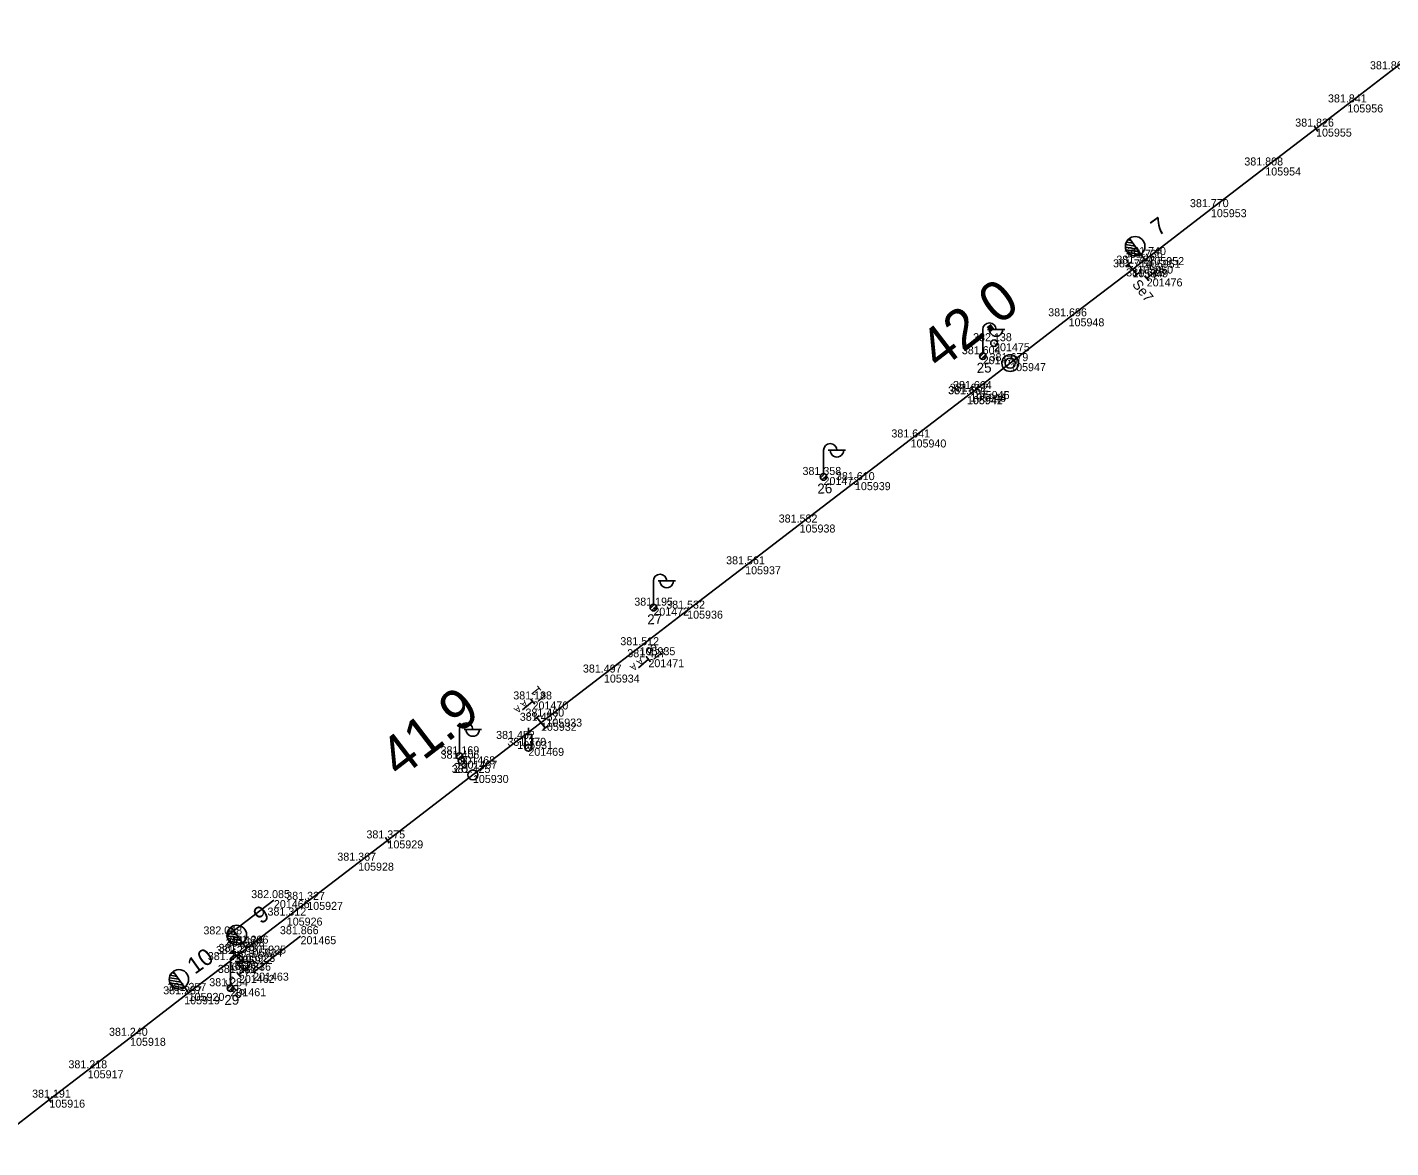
# Model space of a CAD drawing. Extents: x -514522 to -512811, y -1144589 to -1143575.
# Drawn here: x -513869.6 to -513665.2, y -1144029.6 to -1143861.6 of the extents above; entities that cross this region are included whole.
import ezdxf

# ---------------------------------------------------------------- set-up
doc = ezdxf.new("R2010")
doc.units = 0
for name, color, linetype in [('Vrstva 1', 7, 'Continuous'), ('Vrstva 17', 7, 'Continuous'), ('Vrstva 2', 7, 'Continuous'), ('Vrstva 25', 7, 'Continuous'), ('Vrstva 3', 7, 'Continuous'), ('Vrstva 50', 7, 'Continuous'), ('Vrstva 6', 7, 'Continuous'), ('Vrstva 60', 7, 'Continuous'), ('Vrstva 61', 7, 'Continuous'), ('Vrstva 7', 7, 'Continuous')]:
    doc.layers.add(name, color=color, linetype=linetype)

msp = doc.modelspace()

# ---------------------------------------------------------------- linework, layer by layer
at = {"layer": 'Vrstva 1'}
for p, q in [((-513665.21, -1143868.2), (-513656.61, -1143861.6)), ((-513671.7, -1143873.17), (-513665.21, -1143868.2)), ((-513676.4, -1143876.79), (-513671.7, -1143873.17)), ((-513684.01, -1143882.62), (-513676.4, -1143876.79)), ((-513692.16, -1143888.87), (-513684.01, -1143882.62)), ((-513701.53, -1143896.05), (-513692.16, -1143888.87)), ((-513703.19, -1143897.33), (-513702.07, -1143896.46)), ((-513702.07, -1143896.46), (-513701.53, -1143896.05)), ((-513713.49, -1143905.23), (-513703.93, -1143897.89)), ((-513703.93, -1143897.89), (-513703.19, -1143897.33)), ((-513722.25, -1143911.95), (-513713.49, -1143905.23)), ((-513727.7, -1143916.13), (-513722.25, -1143911.95)), ((-513737.18, -1143923.4), (-513728.7, -1143916.89)), ((-513728.7, -1143916.89), (-513728.23, -1143916.53)), ((-513728.23, -1143916.53), (-513727.7, -1143916.13)), ((-513745.52, -1143929.79), (-513737.18, -1143923.4)), ((-513753.81, -1143936.14), (-513745.52, -1143929.79)), ((-513761.98, -1143942.4), (-513753.81, -1143936.14)), ((-513770.67, -1143949.05), (-513761.98, -1143942.4)), ((-513777.8, -1143954.53), (-513770.67, -1143949.05)), ((-513783.15, -1143958.63), (-513777.8, -1143954.53)), ((-513791.78, -1143965.23), (-513783.15, -1143958.63)), ((-513796.14, -1143968.58), (-513792.59, -1143965.86)), ((-513792.59, -1143965.86), (-513791.78, -1143965.23)), ((-513802.79, -1143973.68), (-513796.14, -1143968.58)), ((-513815.6, -1143983.49), (-513802.79, -1143973.68)), ((-513819.99, -1143986.83), (-513815.6, -1143983.49)), ((-513827.62, -1143992.7), (-513819.99, -1143986.83)), ((-513830.69, -1143995.06), (-513827.62, -1143992.7)), ((-513836.16, -1143999.26), (-513830.69, -1143995.06)), ((-513836.73, -1143999.7), (-513836.16, -1143999.26)), ((-513839.38, -1144001.73), (-513838.19, -1144000.81)), ((-513838.19, -1144000.81), (-513837.78, -1144000.5)), ((-513837.78, -1144000.5), (-513836.73, -1143999.7)), ((-513845.4, -1144006.35), (-513839.38, -1144001.73)), ((-513854.18, -1144013.08), (-513846.07, -1144006.86)), ((-513846.07, -1144006.86), (-513845.4, -1144006.35)), ((-513860.53, -1144017.95), (-513854.18, -1144013.08)), ((-513866.28, -1144022.35), (-513860.53, -1144017.95)), ((-513875.66, -1144029.56), (-513866.28, -1144022.35))]:
    msp.add_line(p, q, dxfattribs=at)
at = {"layer": 'Vrstva 17'}
for p, q in [((-513839.76, -1143997.88), (-513832.62, -1143992.44)), ((-513835.74, -1144003.31), (-513828.63, -1143997.85))]:
    msp.add_line(p, q, dxfattribs=at)
at = {"layer": 'Vrstva 2'}
for p, q in [((-513676.13, -1143877.21), (-513676.68, -1143876.37)), ((-513703.22, -1143894.85), (-513704.97, -1143894.56)), ((-513703.53, -1143894.42), (-513704.95, -1143894.18)), ((-513702.91, -1143895.28), (-513704.88, -1143894.95)), ((-513703.84, -1143893.99), (-513704.84, -1143893.82)), ((-513704.15, -1143893.56), (-513704.62, -1143893.48)), ((-513702.66, -1143895.63), (-513704.37, -1143893.25)), ((-513704.37, -1143893.25), (-513702.66, -1143895.63)), ((-513702.76, -1143895.68), (-513704.63, -1143895.38)), ((-513702.66, -1143895.63), (-513702.07, -1143896.46)), ((-513702.66, -1143895.63), (-513702.66, -1143895.63)), ((-513815.32, -1143983.91), (-513815.87, -1143983.07)), ((-513838.19, -1143997.65), (-513839.62, -1143997.41)), ((-513838.5, -1143997.22), (-513839.5, -1143997.05)), ((-513838.81, -1143996.79), (-513839.28, -1143996.71)), ((-513837.33, -1143998.86), (-513839.03, -1143996.48)), ((-513839.03, -1143996.48), (-513837.33, -1143998.86)), ((-513837.88, -1143998.08), (-513839.63, -1143997.79)), ((-513837.57, -1143998.51), (-513839.54, -1143998.19)), ((-513837.42, -1143998.92), (-513839.3, -1143998.61)), ((-513837.33, -1143998.86), (-513836.73, -1143999.7)), ((-513837.33, -1143998.86), (-513837.33, -1143998.86)), ((-513847.48, -1144003.44), (-513847.95, -1144003.36)), ((-513846, -1144005.51), (-513847.7, -1144003.13)), ((-513847.7, -1144003.13), (-513846, -1144005.51)), ((-513846.55, -1144004.73), (-513848.31, -1144004.44)), ((-513846.86, -1144004.3), (-513848.29, -1144004.07)), ((-513846.25, -1144005.17), (-513848.22, -1144004.84)), ((-513847.17, -1144003.87), (-513848.18, -1144003.71)), ((-513846.1, -1144005.57), (-513847.97, -1144005.26)), ((-513846, -1144005.51), (-513845.4, -1144006.35)), ((-513846, -1144005.51), (-513846, -1144005.51)), ((-513866, -1144022.77), (-513866.55, -1144021.94))]:
    msp.add_line(p, q, dxfattribs=at)
for centre in [(-513703.52, -1143894.43), (-513838.18, -1143997.66), (-513846.86, -1144004.32)]:
    msp.add_circle(centre, 1.46, dxfattribs=at)
for centre in [(-513703.52, -1143894.44), (-513838.18, -1143997.67), (-513846.85, -1144004.32)]:
    msp.add_arc(centre, 1.46, 125.6292, 305.5901, dxfattribs=at)
at = {"layer": 'Vrstva 25'}
for p, q in [((-513726.36, -1143910.41), (-513726.36, -1143906.91)), ((-513725.66, -1143906.91), (-513723.06, -1143906.91)), ((-513726.84, -1143911.05), (-513726.22, -1143910.43)), ((-513726.6, -1143911.34), (-513725.92, -1143910.67)), ((-513750.23, -1143928.51), (-513750.23, -1143925.01)), ((-513749.53, -1143925.01), (-513746.93, -1143925.01)), ((-513750.71, -1143929.16), (-513750.09, -1143928.53)), ((-513750.47, -1143929.45), (-513749.79, -1143928.77)), ((-513775.74, -1143948.1), (-513775.74, -1143944.6)), ((-513775.04, -1143944.6), (-513772.44, -1143944.6)), ((-513776.22, -1143948.74), (-513775.6, -1143948.12)), ((-513775.98, -1143949.03), (-513775.3, -1143948.36)), ((-513804.81, -1143970.38), (-513804.81, -1143966.88)), ((-513804.11, -1143966.88), (-513801.51, -1143966.88)), ((-513805.29, -1143971.03), (-513804.67, -1143970.41)), ((-513805.05, -1143971.32), (-513804.37, -1143970.64)), ((-513839.14, -1144005.15), (-513839.14, -1144001.65)), ((-513838.44, -1144001.65), (-513835.84, -1144001.65)), ((-513839.61, -1144005.8), (-513838.99, -1144005.18)), ((-513839.38, -1144006.09), (-513838.7, -1144005.41))]:
    msp.add_line(p, q, dxfattribs=at)
for centre in [(-513726.36, -1143910.91), (-513750.23, -1143929.01), (-513775.74, -1143948.6), (-513804.81, -1143970.88), (-513839.14, -1144005.65)]:
    msp.add_circle(centre, 0.5, dxfattribs=at)
for centre, start, end in [((-513725.36, -1143906.91), 0, 180), ((-513724.36, -1143906.92), 179.2974, 0.7026), ((-513749.23, -1143925.01), 0, 180), ((-513748.23, -1143925.02), 179.2974, 0.7026), ((-513774.74, -1143944.6), 0, 180), ((-513773.74, -1143944.61), 179.2974, 0.7026), ((-513803.81, -1143966.88), 0, 180), ((-513802.81, -1143966.89), 179.2974, 0.7026), ((-513838.14, -1144001.65), 0, 180), ((-513837.14, -1144001.67), 179.2974, 0.7026)]:
    msp.add_arc(centre, 1, start, end, dxfattribs=at)
at = {"layer": 'Vrstva 3'}
for p, q in [((-513704.95, -1143897.45), (-513704.19, -1143896.8)), ((-513704.57, -1143897.13), (-513703.28, -1143898.66)), ((-513703.67, -1143898.98), (-513702.9, -1143898.34)), ((-513793.61, -1143965.41), (-513792.84, -1143964.77)), ((-513793.23, -1143965.09), (-513791.94, -1143966.62)), ((-513792.33, -1143966.94), (-513791.56, -1143966.3)), ((-513839.21, -1144000.37), (-513838.45, -1143999.73)), ((-513838.83, -1144000.05), (-513837.54, -1144001.58)), ((-513837.93, -1144001.9), (-513837.16, -1144001.26))]:
    msp.add_line(p, q, dxfattribs=at)
at = {"layer": 'Vrstva 50'}
for p, q in [((-513794.48, -1143966.61), (-513794.48, -1143967.61)), ((-513794.43, -1143969.61), (-513794.53, -1143969.61))]:
    msp.add_line(p, q, dxfattribs=at)
msp.add_lwpolyline([(-513794.98, -1143969.61), (-513794.98, -1143967.61), (-513793.97, -1143967.61), (-513793.97, -1143969.61)], dxfattribs=at)
msp.add_circle((-513794.48, -1143969.61), 0.506, dxfattribs=at)
at = {"layer": 'Vrstva 6'}
for p, q in [((-513702.1, -1143898.86), (-513701.45, -1143899.63)), ((-513700.26, -1143897.97), (-513701.78, -1143899.25)), ((-513777.99, -1143957.6), (-513776.48, -1143956.32)), ((-513776.15, -1143956.71), (-513776.8, -1143955.94)), ((-513795.37, -1143963.93), (-513793.85, -1143962.66)), ((-513793.53, -1143963.05), (-513794.17, -1143962.28)), ((-513838.2, -1144003.27), (-513837.55, -1144004.03)), ((-513836.36, -1144002.38), (-513837.87, -1144003.65))]:
    msp.add_line(p, q, dxfattribs=at)
at = {"layer": 'Vrstva 60'}
for p, q in [((-513671.7, -1143873.17), (-513671.7, -1143873.17)), ((-513676.4, -1143876.79), (-513676.4, -1143876.79)), ((-513684.01, -1143882.62), (-513684.01, -1143882.62)), ((-513692.16, -1143888.87), (-513692.16, -1143888.87)), ((-513702.07, -1143896.46), (-513702.07, -1143896.46)), ((-513701.53, -1143896.05), (-513701.53, -1143896.05)), ((-513703.93, -1143897.89), (-513703.93, -1143897.89)), ((-513703.19, -1143897.33), (-513703.19, -1143897.33)), ((-513701.78, -1143899.25), (-513701.78, -1143899.25)), ((-513713.49, -1143905.23), (-513713.49, -1143905.23)), ((-513724.67, -1143908.96), (-513724.67, -1143908.96)), ((-513726.36, -1143910.91), (-513726.36, -1143910.91)), ((-513722.25, -1143911.95), (-513722.25, -1143911.95)), ((-513728.74, -1143916.92), (-513728.74, -1143916.92)), ((-513728.7, -1143916.89), (-513728.7, -1143916.89)), ((-513728.23, -1143916.53), (-513728.23, -1143916.53)), ((-513728.22, -1143916.53), (-513728.22, -1143916.53)), ((-513727.7, -1143916.13), (-513727.7, -1143916.13)), ((-513727.7, -1143916.13), (-513727.7, -1143916.13)), ((-513737.18, -1143923.4), (-513737.18, -1143923.4)), ((-513750.23, -1143929.01), (-513750.23, -1143929.01)), ((-513745.52, -1143929.79), (-513745.52, -1143929.79)), ((-513753.81, -1143936.14), (-513753.81, -1143936.14)), ((-513761.98, -1143942.4), (-513761.98, -1143942.4)), ((-513775.74, -1143948.6), (-513775.74, -1143948.6)), ((-513770.67, -1143949.05), (-513770.67, -1143949.05)), ((-513777.8, -1143954.53), (-513777.8, -1143954.53)), ((-513776.48, -1143956.32), (-513776.48, -1143956.32)), ((-513783.15, -1143958.63), (-513783.15, -1143958.63)), ((-513793.85, -1143962.66), (-513793.85, -1143962.66)), ((-513792.59, -1143965.86), (-513792.59, -1143965.86)), ((-513791.78, -1143965.23), (-513791.78, -1143965.23)), ((-513796.14, -1143968.58), (-513796.14, -1143968.58)), ((-513794.48, -1143969.61), (-513794.48, -1143969.61)), ((-513804.81, -1143970.88), (-513804.81, -1143970.88)), ((-513804.49, -1143971.54), (-513804.49, -1143971.54)), ((-513802.79, -1143973.68), (-513802.79, -1143973.68)), ((-513815.6, -1143983.49), (-513815.6, -1143983.49)), ((-513819.99, -1143986.83), (-513819.99, -1143986.83)), ((-513832.62, -1143992.44), (-513832.62, -1143992.44)), ((-513827.62, -1143992.7), (-513827.62, -1143992.7)), ((-513830.69, -1143995.06), (-513830.69, -1143995.06)), ((-513839.76, -1143997.88), (-513839.76, -1143997.88)), ((-513836.16, -1143999.26), (-513836.16, -1143999.26)), ((-513828.63, -1143997.85), (-513828.63, -1143997.85)), ((-513838.19, -1144000.81), (-513838.19, -1144000.81)), ((-513837.78, -1144000.5), (-513837.78, -1144000.5)), ((-513836.73, -1143999.7), (-513836.73, -1143999.7)), ((-513839.38, -1144001.73), (-513839.38, -1144001.73)), ((-513835.74, -1144003.31), (-513835.74, -1144003.31)), ((-513837.87, -1144003.65), (-513837.87, -1144003.65)), ((-513846.07, -1144006.86), (-513846.07, -1144006.86)), ((-513845.4, -1144006.35), (-513845.4, -1144006.35)), ((-513839.14, -1144005.65), (-513839.14, -1144005.65)), ((-513854.18, -1144013.08), (-513854.18, -1144013.08)), ((-513860.53, -1144017.95), (-513860.53, -1144017.95)), ((-513866.28, -1144022.35), (-513866.28, -1144022.35))]:
    msp.add_line(p, q, dxfattribs=at)
at = {"layer": 'Vrstva 7'}
for p, q in [((-513724.72, -1143908.96), (-513724.62, -1143908.96)), ((-513804.54, -1143971.54), (-513804.44, -1143971.54))]:
    msp.add_line(p, q, dxfattribs=at)
for centre, radius in [((-513724.67, -1143908.96), 0.5), ((-513722.25, -1143911.95), 1.25), ((-513722.25, -1143911.95), 0.752), ((-513804.49, -1143971.54), 0.5), ((-513802.79, -1143973.68), 0.75)]:
    msp.add_circle(centre, radius, dxfattribs=at)

# ---------------------------------------------------------------- texts
at = {"layer": 'Vrstva 2'}
for s, p in [('7', (-513700.04, -1143892.99)), ('9', (-513834.58, -1143996.13)), ('10', (-513844.47, -1144003.65))]:
    msp.add_text(s, height=2.5, rotation=35.5807, dxfattribs=at).set_placement(p)
at = {"layer": 'Vrstva 25'}
for s, p in [('25', (-513727.25, -1143913.42)), ('26', (-513751.13, -1143931.52)), ('27', (-513776.63, -1143951.11)), ('28', (-513805.7, -1143973.4)), ('29', (-513840.03, -1144008.17))]:
    msp.add_text(s, height=1.5, rotation=1.9463, dxfattribs=at).set_placement(p)
at = {"layer": 'Vrstva 6'}
for s, height, rotation, p in [('  A A ', 1, 40, (-513701.13, -1143900.01)), ('Se7', 1.5, 308.4684, (-513704.05, -1143900.16)), ('L3', 1.5, 128.4684, (-513774.37, -1143955.61)), ('  A A ', 1, 220, (-513777.12, -1143955.56)), ('L1', 1.5, 128.4684, (-513791.74, -1143961.94)), ('  A A ', 1, 220, (-513794.5, -1143961.9)), ('  A A ', 1, 40, (-513837.23, -1144004.42)), ('Se8', 1.5, 308.4684, (-513840.15, -1144004.56))]:
    msp.add_text(s, height=height, rotation=rotation, dxfattribs=at).set_placement(p)
at = {"layer": 'Vrstva 60'}
for s, p in [('105956', (-513671.7, -1143874.37)), ('105955', (-513676.4, -1143877.99)), ('105954', (-513684.01, -1143883.82)), ('105953', (-513692.16, -1143890.07)), ('105951', (-513702.07, -1143897.66)), ('105952', (-513701.53, -1143897.25)), ('105949', (-513703.93, -1143899.09)), ('105950', (-513703.19, -1143898.53)), ('201476', (-513701.78, -1143900.45)), ('105948', (-513713.49, -1143906.43)), ('201475', (-513724.67, -1143910.16)), ('201474', (-513726.36, -1143912.11)), ('105947', (-513722.25, -1143913.15)), ('105941', (-513728.74, -1143918.12)), ('105942', (-513728.7, -1143918.09)), ('105943', (-513728.23, -1143917.73)), ('105944', (-513728.22, -1143917.73)), ('105945', (-513727.7, -1143917.33)), ('105946', (-513727.7, -1143917.33)), ('105940', (-513737.18, -1143924.59)), ('201473', (-513750.23, -1143930.21)), ('105939', (-513745.52, -1143930.99)), ('105938', (-513753.81, -1143937.34)), ('105937', (-513761.98, -1143943.6)), ('201472', (-513775.74, -1143949.8)), ('105936', (-513770.67, -1143950.25)), ('105935', (-513777.8, -1143955.73)), ('201471', (-513776.48, -1143957.53)), ('105934', (-513783.15, -1143959.83)), ('201470', (-513793.85, -1143963.86)), ('105932', (-513792.59, -1143967.06)), ('105933', (-513791.78, -1143966.43)), ('105931', (-513796.14, -1143969.78)), ('201468', (-513804.81, -1143972.08)), ('201469', (-513794.48, -1143970.81)), ('201467', (-513804.49, -1143972.74)), ('105930', (-513802.79, -1143974.88)), ('105929', (-513815.6, -1143984.69)), ('105928', (-513819.99, -1143988.03)), ('201466', (-513832.62, -1143993.64)), ('105927', (-513827.62, -1143993.9)), ('105926', (-513830.69, -1143996.26)), ('201464', (-513839.76, -1143999.08)), ('105925', (-513836.16, -1144000.46)), ('201465', (-513828.63, -1143999.05)), ('105922', (-513838.19, -1144002.02)), ('105923', (-513837.78, -1144001.7)), ('105924', (-513836.73, -1144000.9)), ('105921', (-513839.38, -1144002.93)), ('201463', (-513835.74, -1144004.51)), ('201462', (-513837.87, -1144004.85)), ('105919', (-513846.07, -1144008.06)), ('105920', (-513845.4, -1144007.55)), ('201461', (-513839.14, -1144006.85)), ('105918', (-513854.18, -1144014.28)), ('105917', (-513860.53, -1144019.15)), ('105916', (-513866.28, -1144023.55))]:
    msp.add_text(s, height=1.2, dxfattribs=at).set_placement(p)
at = {"layer": 'Vrstva 61'}
for s, p in [('381.862', (-513668.32, -1143867.9)), ('381.841', (-513674.61, -1143872.87)), ('381.826', (-513679.52, -1143876.49)), ('381.808', (-513687.15, -1143882.32)), ('381.770', (-513695.3, -1143888.57)), ('381.736', (-513705.19, -1143896.16)), ('381.740', (-513704.7, -1143895.75)), ('381.714', (-513706.84, -1143897.59)), ('381.722', (-513706.34, -1143897.03)), ('381.676', (-513704.87, -1143898.95)), ('381.696', (-513716.55, -1143904.93)), ('382.138', (-513727.81, -1143908.66)), ('381.604', (-513729.5, -1143910.61)), ('381.679', (-513725.34, -1143911.65)), ('381.661', (-513731.56, -1143916.62)), ('381.661', (-513731.53, -1143916.59)), ('381.662', (-513731.31, -1143916.23)), ('381.662', (-513731.31, -1143916.23)), ('381.664', (-513730.82, -1143915.83)), ('381.664', (-513730.82, -1143915.83)), ('381.641', (-513740.06, -1143923.09)), ('381.358', (-513753.38, -1143928.71)), ('381.610', (-513748.37, -1143929.49)), ('381.582', (-513756.95, -1143935.84)), ('381.561', (-513764.83, -1143942.1)), ('381.195', (-513778.6, -1143948.3)), ('381.532', (-513773.81, -1143948.75)), ('381.512', (-513780.69, -1143954.23)), ('381.427', (-513779.65, -1143956.03)), ('381.497', (-513786.3, -1143958.33)), ('381.188', (-513796.74, -1143962.36)), ('381.457', (-513795.76, -1143965.56)), ('381.460', (-513794.91, -1143964.93)), ('381.452', (-513799.31, -1143968.28)), ('381.370', (-513797.62, -1143969.31)), ('381.169', (-513807.64, -1143970.58)), ('381.406', (-513807.63, -1143971.24)), ('381.425', (-513805.97, -1143973.38)), ('381.375', (-513818.75, -1143983.19)), ('381.367', (-513823.11, -1143986.53)), ('382.085', (-513836.02, -1143992.14)), ('381.327', (-513830.77, -1143992.4)), ('381.312', (-513833.58, -1143994.76)), ('382.048', (-513843.19, -1143997.58)), ('381.866', (-513831.72, -1143997.55)), ('381.279', (-513841.31, -1144000.52)), ('381.283', (-513840.92, -1144000.2)), ('381.293', (-513839.84, -1143999.4)), ('381.296', (-513839.24, -1143998.96)), ('381.272', (-513842.53, -1144001.43)), ('381.232', (-513841.02, -1144003.35)), ('381.836', (-513838.86, -1144003.01)), ('381.257', (-513849.22, -1144006.56)), ('381.257', (-513848.55, -1144006.05)), ('381.284', (-513842.31, -1144005.35)), ('381.240', (-513857.34, -1144012.78)), ('381.218', (-513863.42, -1144017.65)), ('381.191', (-513868.87, -1144022.05))]:
    msp.add_text(s, height=1.2, dxfattribs=at).set_placement(p)
at = {"layer": 'Vrstva 7'}
for s, p in [('42.0', (-513732.86, -1143913.16)), ('41.9', (-513813.77, -1143974.34))]:
    msp.add_text(s, height=6, rotation=37.535, dxfattribs=at).set_placement(p)

doc.saveas('drawing.dxf')
